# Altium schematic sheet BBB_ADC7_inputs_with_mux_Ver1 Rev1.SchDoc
size E
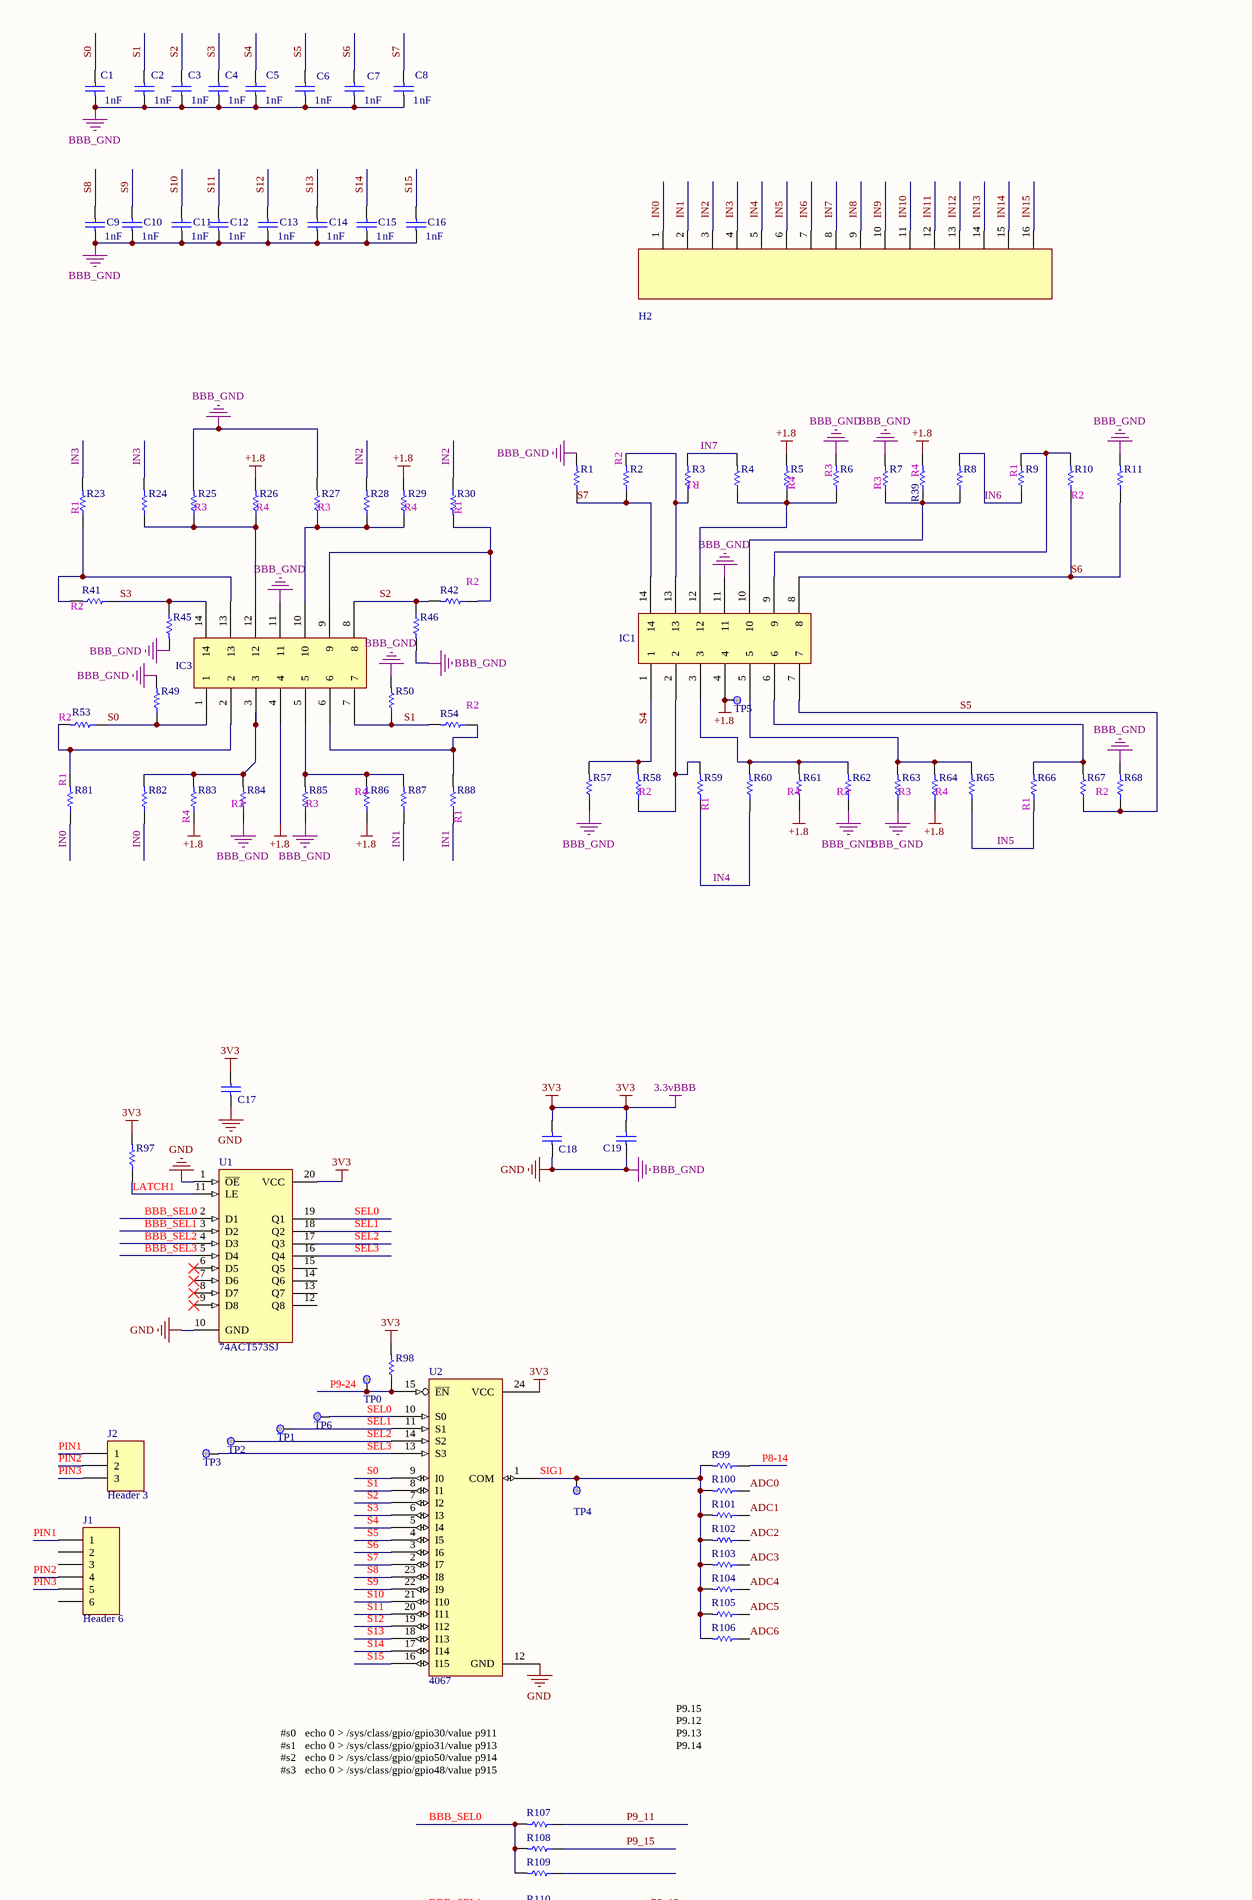
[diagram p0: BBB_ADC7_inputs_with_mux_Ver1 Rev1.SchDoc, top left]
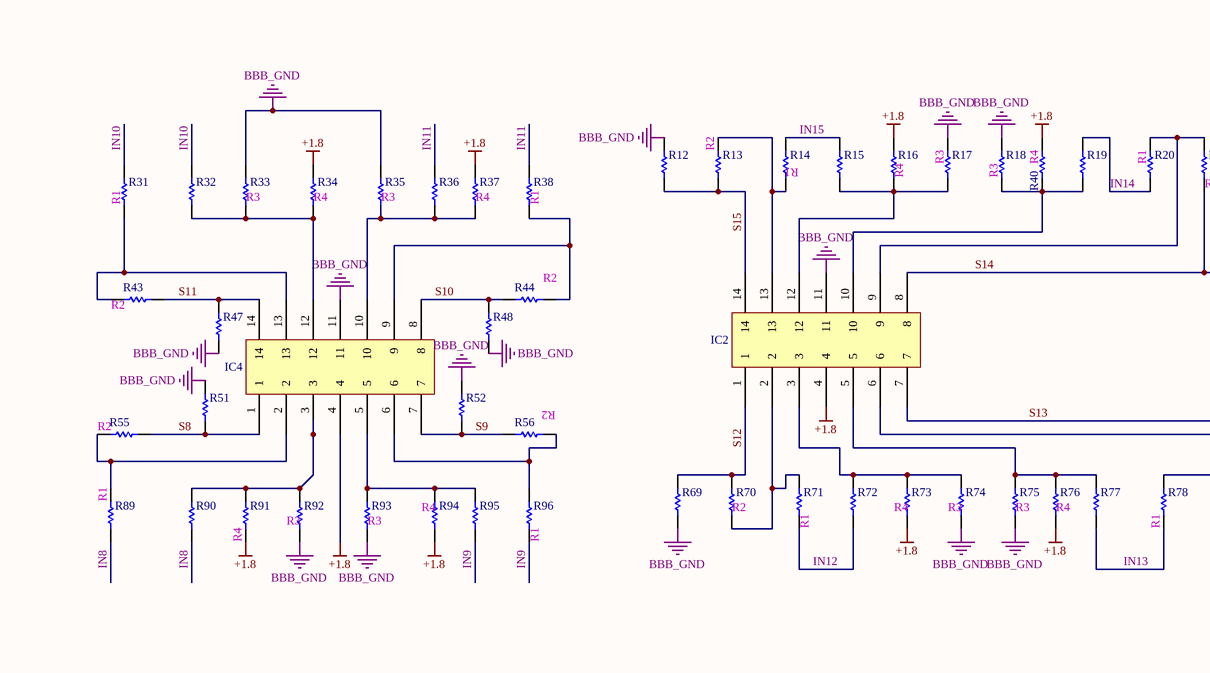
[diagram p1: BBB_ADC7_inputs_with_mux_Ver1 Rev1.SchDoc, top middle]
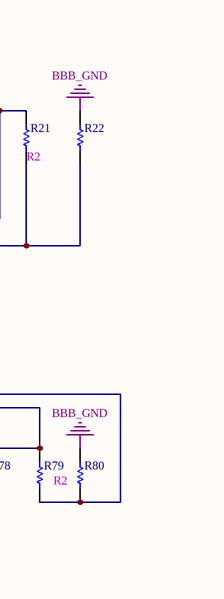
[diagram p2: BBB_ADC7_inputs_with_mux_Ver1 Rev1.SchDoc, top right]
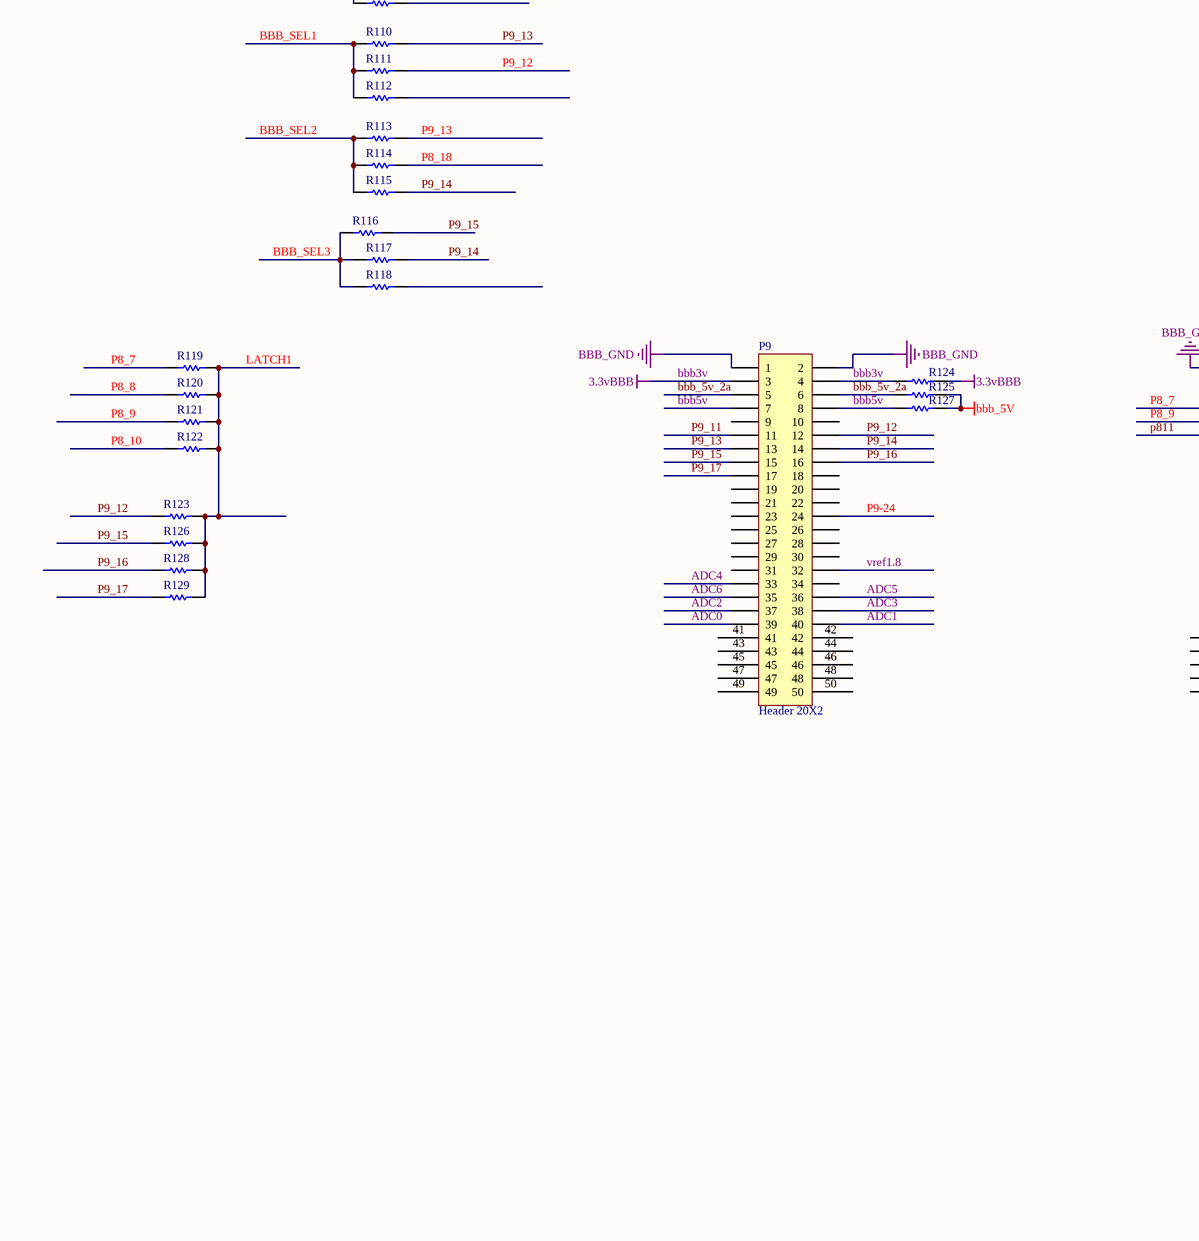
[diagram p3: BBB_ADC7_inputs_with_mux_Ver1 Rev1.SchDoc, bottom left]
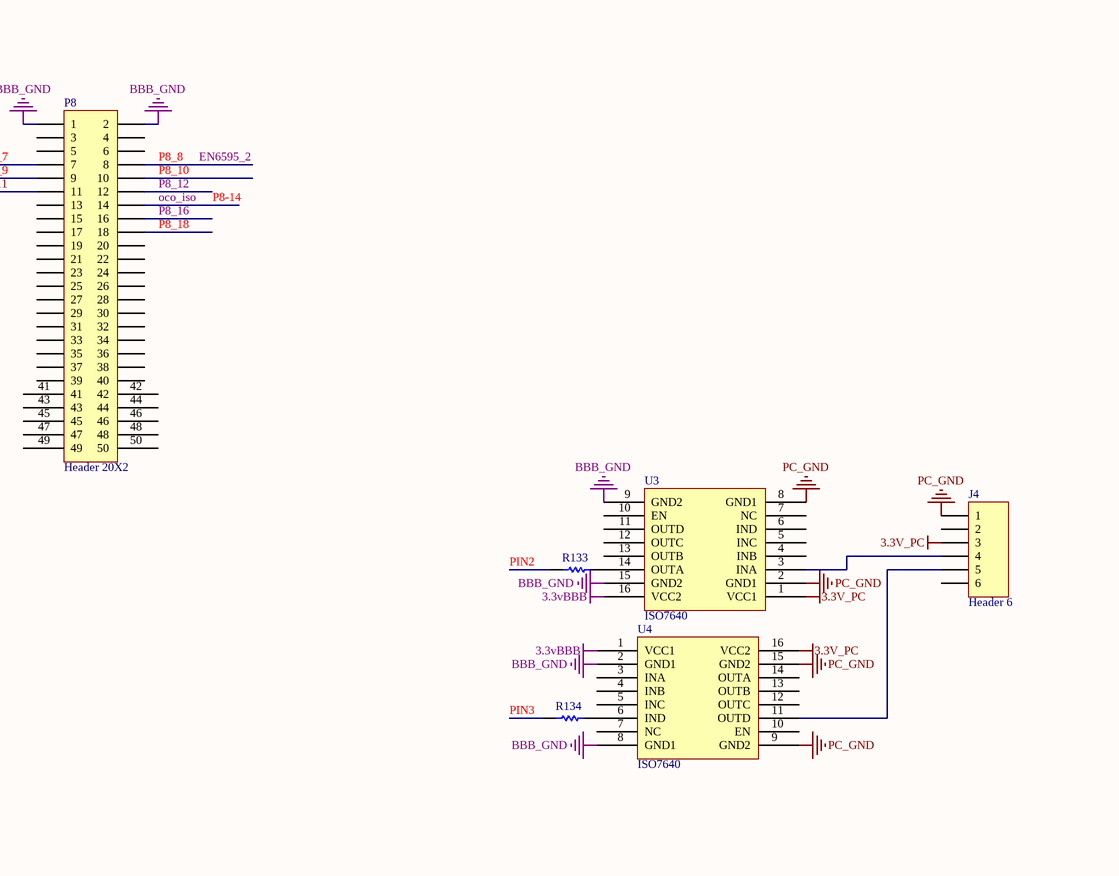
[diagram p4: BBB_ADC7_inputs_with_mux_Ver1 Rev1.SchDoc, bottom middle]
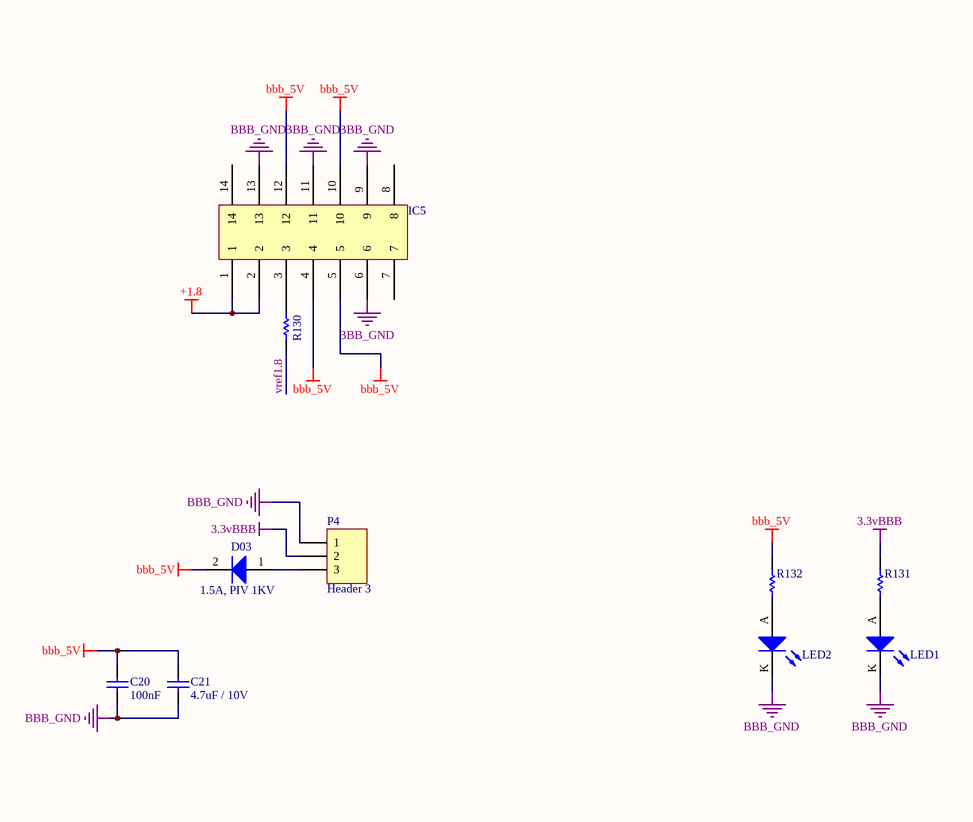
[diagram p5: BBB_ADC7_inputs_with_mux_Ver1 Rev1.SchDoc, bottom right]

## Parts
C1  Units of Capacitance: nF  Capacitance: 1  [C0402]  (hidden comment: CAPACITOR NONPOLAR SMT)
C2  Units of Capacitance: nF  Capacitance: 1  [C0402]  (hidden comment: CAPACITOR NONPOLAR SMT)
C3  Units of Capacitance: nF  Capacitance: 1  [C0402]  (hidden comment: CAPACITOR NONPOLAR SMT)
C4  Units of Capacitance: nF  Capacitance: 1  [C0402]  (hidden comment: CAPACITOR NONPOLAR SMT)
C5  Units of Capacitance: nF  Capacitance: 1  [C0402]  (hidden comment: CAPACITOR NONPOLAR SMT)
C6  Units of Capacitance: nF  Capacitance: 1  [C0402]  (hidden comment: CAPACITOR NONPOLAR SMT)
C7  Units of Capacitance: nF  Capacitance: 1  [C0402]  (hidden comment: CAPACITOR NONPOLAR SMT)
C8  Units of Capacitance: nF  Capacitance: 1  [C0402]  (hidden comment: CAPACITOR NONPOLAR SMT)
C9  Units of Capacitance: nF  Capacitance: 1  [C0402]  (hidden comment: CAPACITOR NONPOLAR SMT)
C10  Units of Capacitance: nF  Capacitance: 1  [C0402]  (hidden comment: CAPACITOR NONPOLAR SMT)
C11  Units of Capacitance: nF  Capacitance: 1  [C0402]  (hidden comment: CAPACITOR NONPOLAR SMT)
C12  Units of Capacitance: nF  Capacitance: 1  [C0402]  (hidden comment: CAPACITOR NONPOLAR SMT)
C13  Units of Capacitance: nF  Capacitance: 1  [C0402]  (hidden comment: CAPACITOR NONPOLAR SMT)
C14  Units of Capacitance: nF  Capacitance: 1  [C0402]  (hidden comment: CAPACITOR NONPOLAR SMT)
C15  Units of Capacitance: nF  Capacitance: 1  [C0402]  (hidden comment: CAPACITOR NONPOLAR SMT)
C16  Units of Capacitance: nF  Capacitance: 1  [C0402]  (hidden comment: CAPACITOR NONPOLAR SMT)
C17  4.7uF, 10V  [C0603]  (value not drawn)
C18  4.7uF, 10V  [C0603]  (value not drawn)
C19  4.7uF, 10V  [C0603]  (value not drawn)
C20  100nF  [C0603]
C21  4.7uF / 10V  [C0603]
D03  1.5A, PIV 1KV  [DIODE_DO-214AA(SMB)]
H2  connector 16 pin male_ stright  [16 pin male stright]  (value not drawn)
IC1  OPamp  [SOIC-14]  (value not drawn)
IC2  OPamp  [SOIC-14]  (value not drawn)
IC3  OPamp  [SOIC-14]  (value not drawn)
IC4  OPamp  [SOIC-14]  (value not drawn)
IC5  OPamp  [SOIC-14]  (value not drawn)
J1  Header 6  [HDR1X6]
J2  Header 3  [HDR1X3]
J4  Header 6  [HDR1X6]
LED1  LED  [0537, LED, 1206]  (value not drawn)
LED2  LED  [0537, LED, 1206]  (value not drawn)
P4  Header 3  [HDR1X3]
P8  Header 20X2  [BBBHEADERNOHOLE]
P9  Header 20X2  [BBBHEADERNOHOLE]
R1  Resistor SMD 0603, 100 k Ohm, +/-5%, 1/10W  [0603]  (value not drawn)
R2  Resistor SMD 0603, 1.5 k Ohm, +/-5%, 1/10W  [0603]  (value not drawn)
R3  Resistor SMD 0603, 9.1 k Ohm, +/-5%, 1/10W  [0603]  (value not drawn)
R4  open  [0603]  (value not drawn)
R5  Resistor SMD 0603, 6.8 k Ohm, +/-1%, 1/10W  [0603]  (value not drawn)
R6  Resistor SMD 0603, 4.7 k Ohm, +/-5%, 1/10W  [0603]  (value not drawn)
R7  Resistor SMD 0603, 4.7 k Ohm, +/-5%, 1/10W  [0603]  (value not drawn)
R8  open  [0603]  (value not drawn)
R9  Resistor SMD 0603, 9.1 k Ohm, +/-5%, 1/10W  [0603]  (value not drawn)
R10  Resistor SMD 0603, 1.5 k Ohm, +/-5%, 1/10W  [0603]  (value not drawn)
R11  Resistor SMD 0603, 100 k Ohm, +/-5%, 1/10W  [0603]  (value not drawn)
R12  Resistor SMD 0603, 100 k Ohm, +/-5%, 1/10W  [0603]  (value not drawn)
R13  Resistor SMD 0603, 1.5 k Ohm, +/-5%, 1/10W  [0603]  (value not drawn)
R14  Resistor SMD 0603, 9.1 k Ohm, +/-5%, 1/10W  [0603]  (value not drawn)
R15  open  [0603]  (value not drawn)
R16  Resistor SMD 0603, 6.8 k Ohm, +/-1%, 1/10W  [0603]  (value not drawn)
R17  Resistor SMD 0603, 4.7 k Ohm, +/-5%, 1/10W  [0603]  (value not drawn)
R18  Resistor SMD 0603, 4.7 k Ohm, +/-5%, 1/10W  [0603]  (value not drawn)
R19  open  [0603]  (value not drawn)
R20  Resistor SMD 0603, 9.1 k Ohm, +/-5%, 1/10W  [0603]  (value not drawn)
R21  Resistor SMD 0603, 1.5 k Ohm, +/-5%, 1/10W  [0603]  (value not drawn)
R22  Resistor SMD 0603, 100 k Ohm, +/-5%, 1/10W  [0603]  (value not drawn)
R23  Resistor SMD 0603, 9.1 k Ohm, +/-5%, 1/10W  [0603]  (value not drawn)
R24  OPEN  [0603]  (value not drawn)
R25  Resistor SMD 0603, 4.7 k Ohm, +/-5%, 1/10W  [0603]  (value not drawn)
R26  Resistor SMD 0603, 6.8 k Ohm, +/-1%, 1/10W  [0603]  (value not drawn)
R27  Resistor SMD 0603, 4.7 k Ohm, +/-5%, 1/10W  [0603]  (value not drawn)
R28  OPEN  [0603]  (value not drawn)
R29  Resistor SMD 0603, 6.8 k Ohm, +/-1%, 1/10W  [0603]  (value not drawn)
R30  Resistor SMD 0603, 9.1 k Ohm, +/-5%, 1/10W  [0603]  (value not drawn)
R31  Resistor SMD 0603, 9.1 k Ohm, +/-5%, 1/10W  [0603]  (value not drawn)
R32  OPEN  [0603]  (value not drawn)
R33  Resistor SMD 0603, 4.7 k Ohm, +/-5%, 1/10W  [0603]  (value not drawn)
R34  Resistor SMD 0603, 6.8 k Ohm, +/-1%, 1/10W  [0603]  (value not drawn)
R35  Resistor SMD 0603, 4.7 k Ohm, +/-5%, 1/10W  [0603]  (value not drawn)
R36  OPEN  [0603]  (value not drawn)
R37  Resistor SMD 0603, 6.8 k Ohm, +/-1%, 1/10W  [0603]  (value not drawn)
R38  Resistor SMD 0603, 9.1 k Ohm, +/-5%, 1/10W  [0603]  (value not drawn)
R39  Resistor SMD 0603, 6.8 k Ohm, +/-1%, 1/10W  [0603]  (value not drawn)
R40  Resistor SMD 0603, 6.8 k Ohm, +/-1%, 1/10W  [0603]  (value not drawn)
R41  Resistor SMD 0603, 1.5 k Ohm, +/-5%, 1/10W  [0603]  (value not drawn)
R42  Resistor SMD 0603, 1.5 k Ohm, +/-5%, 1/10W  [0603]  (value not drawn)
R43  Resistor SMD 0603, 1.5 k Ohm, +/-5%, 1/10W  [0603]  (value not drawn)
R44  Resistor SMD 0603, 1.5 k Ohm, +/-5%, 1/10W  [0603]  (value not drawn)
R45  Resistor SMD 0603, 100 k Ohm, +/-5%, 1/10W  [0603]  (value not drawn)
R46  Resistor SMD 0603, 100 k Ohm, +/-5%, 1/10W  [0603]  (value not drawn)
R47  Resistor SMD 0603, 100 k Ohm, +/-5%, 1/10W  [0603]  (value not drawn)
R48  Resistor SMD 0603, 100 k Ohm, +/-5%, 1/10W  [0603]  (value not drawn)
R49  Resistor SMD 0603, 100 k Ohm, +/-5%, 1/10W  [0603]  (value not drawn)
R50  Resistor SMD 0603, 100 k Ohm, +/-5%, 1/10W  [0603]  (value not drawn)
R51  Resistor SMD 0603, 100 k Ohm, +/-5%, 1/10W  [0603]  (value not drawn)
R52  Resistor SMD 0603, 100 k Ohm, +/-5%, 1/10W  [0603]  (value not drawn)
R53  Resistor SMD 0603, 1.5 k Ohm, +/-5%, 1/10W  [0603]  (value not drawn)
R54  Resistor SMD 0603, 1.5 k Ohm, +/-5%, 1/10W  [0603]  (value not drawn)
R55  Resistor SMD 0603, 1.5 k Ohm, +/-5%, 1/10W  [0603]  (value not drawn)
R56  Resistor SMD 0603, 1.5 k Ohm, +/-5%, 1/10W  [0603]  (value not drawn)
R57  Resistor SMD 0603, 100 k Ohm, +/-5%, 1/10W  [0603]  (value not drawn)
R58  Resistor SMD 0603, 1.5 k Ohm, +/-5%, 1/10W  [0603]  (value not drawn)
R59  Resistor SMD 0603, 9.1 k Ohm, +/-5%, 1/10W  [0603]  (value not drawn)
R60  open  [0603]  (value not drawn)
R61  Resistor SMD 0603, 6.8 k Ohm, +/-1%, 1/10W  [0603]  (value not drawn)
R62  Resistor SMD 0603, 4.7 k Ohm, +/-5%, 1/10W  [0603]  (value not drawn)
R63  Resistor SMD 0603, 4.7 k Ohm, +/-5%, 1/10W  [0603]  (value not drawn)
R64  Resistor SMD 0603, 6.8 k Ohm, +/-1%, 1/10W  [0603]  (value not drawn)
R65  open  [0603]  (value not drawn)
R66  Resistor SMD 0603, 9.1 k Ohm, +/-5%, 1/10W  [0603]  (value not drawn)
R67  Resistor SMD 0603, 1.5 k Ohm, +/-5%, 1/10W  [0603]  (value not drawn)
R68  Resistor SMD 0603, 100 k Ohm, +/-5%, 1/10W  [0603]  (value not drawn)
R69  Resistor SMD 0603, 100 k Ohm, +/-5%, 1/10W  [0603]  (value not drawn)
R70  Resistor SMD 0603, 1.5 k Ohm, +/-5%, 1/10W  [0603]  (value not drawn)
R71  Resistor SMD 0603, 9.1 k Ohm, +/-5%, 1/10W  [0603]  (value not drawn)
R72  open  [0603]  (value not drawn)
R73  Resistor SMD 0603, 6.8 k Ohm, +/-1%, 1/10W  [0603]  (value not drawn)
R74  Resistor SMD 0603, 4.7 k Ohm, +/-5%, 1/10W  [0603]  (value not drawn)
R75  Resistor SMD 0603, 4.7 k Ohm, +/-5%, 1/10W  [0603]  (value not drawn)
R76  Resistor SMD 0603, 6.8 k Ohm, +/-1%, 1/10W  [0603]  (value not drawn)
R77  open  [0603]  (value not drawn)
R78  Resistor SMD 0603, 9.1 k Ohm, +/-5%, 1/10W  [0603]  (value not drawn)
R79  Resistor SMD 0603, 1.5 k Ohm, +/-5%, 1/10W  [0603]  (value not drawn)
R80  Resistor SMD 0603, 100 k Ohm, +/-5%, 1/10W  [0603]  (value not drawn)
R81  Resistor SMD 0603, 9.1 k Ohm, +/-5%, 1/10W  [0603]  (value not drawn)
R82  OPEN  [0603]  (value not drawn)
R83  Resistor SMD 0603, 6.8 k Ohm, +/-1%, 1/10W  [0603]  (value not drawn)
R84  Resistor SMD 0603, 4.7 k Ohm, +/-5%, 1/10W  [0603]  (value not drawn)
R85  Resistor SMD 0603, 4.7 k Ohm, +/-5%, 1/10W  [0603]  (value not drawn)
R86  Resistor SMD 0603, 6.8 k Ohm, +/-1%, 1/10W  [0603]  (value not drawn)
R87  OPEN  [0603]  (value not drawn)
R88  Resistor SMD 0603, 9.1 k Ohm, +/-5%, 1/10W  [0603]  (value not drawn)
R89  Resistor SMD 0603, 9.1 k Ohm, +/-5%, 1/10W  [0603]  (value not drawn)
R90  OPEN  [0603]  (value not drawn)
R91  Resistor SMD 0603, 6.8 k Ohm, +/-1%, 1/10W  [0603]  (value not drawn)
R92  Resistor SMD 0603, 4.7 k Ohm, +/-5%, 1/10W  [0603]  (value not drawn)
R93  Resistor SMD 0603, 4.7 k Ohm, +/-5%, 1/10W  [0603]  (value not drawn)
R94  Resistor SMD 0603, 6.8 k Ohm, +/-1%, 1/10W  [0603]  (value not drawn)
R95  OPEN  [0603]  (value not drawn)
R96  Resistor SMD 0603, 9.1 k Ohm, +/-5%, 1/10W  [0603]  (value not drawn)
R97  (no value)  [0603]
R98  1Kohm  [0603]  (value not drawn)
R99  1Kohm  [0603]  (value not drawn)
R100  1Kohm  [0603]  (value not drawn)
R101  1Kohm  [0603]  (value not drawn)
R102  1Kohm  [0603]  (value not drawn)
R103  1Kohm  [0603]  (value not drawn)
R104  1Kohm  [0603]  (value not drawn)
R105  1Kohm  [0603]  (value not drawn)
R106  1Kohm  [0603]  (value not drawn)
R107  (no value)  [0603]
R108  (no value)  [0603]
R109  (no value)  [0603]
R110  (no value)  [0603]
R111  (no value)  [0603]
R112  (no value)  [0603]
R113  (no value)  [0603]
R114  (no value)  [0603]
R115  (no value)  [0603]
R116  (no value)  [0603]
R117  (no value)  [0603]
R118  (no value)  [0603]
R119  1Kohm  [0603]  (value not drawn)
R120  1Kohm  [0603]  (value not drawn)
R121  1Kohm  [0603]  (value not drawn)
R122  1Kohm  [0603]  (value not drawn)
R123  1Kohm  [0603]  (value not drawn)
R124  Resistor SMD 0603, 0 Ohm, +/-5%, 1/10W  [0603]  (value not drawn)
R125  Resistor SMD 0603, 0 Ohm, +/-5%, 1/10W  [0603]  (value not drawn)
R126  1Kohm  [0603]  (value not drawn)
R127  Resistor SMD 0603, 0 Ohm, +/-5%, 1/10W  [0603]  (value not drawn)
R128  1Kohm  [0603]  (value not drawn)
R129  1Kohm  [0603]  (value not drawn)
R130  Resistor SMD 0603, 0 Ohm, +/-5%, 1/10W  [0603]  (value not drawn)
R131  Resistor SMD 0603, 4.7 k Ohm, +/-5%, 1/10W  [0603]  (value not drawn)
R132  Resistor SMD 0603, 4.7 k Ohm, +/-5%, 1/10W  [0603]  (value not drawn)
R133  Resistor SMD 0603, 0 Ohm, +/-5%, 1/10W  [0603]  (value not drawn)
R134  Resistor SMD 0603, 0 Ohm, +/-5%, 1/10W  [0603]  (value not drawn)
TP0  TEST PAD  [TP]  (value not drawn)
TP1  TEST PAD  [TP]  (value not drawn)
TP2  TEST PAD  [TP]  (value not drawn)
TP3  TEST PAD  [TP]  (value not drawn)
TP4  TEST PAD  [TP]  (value not drawn)
TP5  TEST PAD  [TP]  (value not drawn)
TP6  TEST PAD  [TP]  (value not drawn)
U1  74ACT573SJ  [sol-20]
U2  4067  [SSOP-24]
U3  ISO7640  [SOIC-16]
U4  ISO7640  [SOIC-16]

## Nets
3.3V_PC: J4.3 U3.1(VCC1) U4.16(VCC2)
+1.8: IC1.4 IC2.4 IC3.4 IC4.4 IC5.1 IC5.2 R5.2 R16.2 R26.2 R29.2 R34.2 R37.2 R39.2 R40.2 R61.1 R64.1 R73.1 R76.1 R83.1 R86.1 R91.1 R94.1 TP5.1
bbb3v: C17.1 C18.1 C19.1 P4.2 P9.3 P9.4 R97.2 R98.2 R124.1 R124.2 R131.2 U1.20(VCC) U2.24(VCC) U3.16(VCC2) U4.1(VCC1)  [also labelled 3.3vBBB, 3V3]
bbb_5V: C20.1 C21.1 D03.2 IC5.4 IC5.5 IC5.10 IC5.12 R125.1 R127.1 R132.2
BBB_GND: C1.2 C2.2 C3.2 C4.2 C5.2 C6.2 C7.2 C8.2 C9.2 C10.2 C11.2 C12.2 C13.2 C14.2 C15.2 C16.2 C17.2 C18.2 C19.2 C20.2 C21.2 IC1.11 IC2.11 IC3.11 IC4.11 IC5.6 IC5.9 IC5.11 IC5.13 LED1.K LED2.K P4.1 P8.1 P8.2 P9.1 P9.2 R1.2 R6.2 R7.2 R11.2 R12.2 R17.2 R18.2 R22.2 R25.2 R27.2 R33.2 R35.2 R45.2 R46.2 R47.2 R48.2 R49.2 R50.2 R51.2 R52.2 R57.1 R62.1 R63.1 R68.2 R69.1 R74.1 R75.1 R80.2 R84.1 R85.1 R92.1 R93.1 U1.1(~{OE}) U1.10(GND) U2.12(GND) U3.9(GND2) U3.15(GND2) U4.2(GND1) U4.8(GND1)  [also labelled GND]
PC_GND: J4.1 U3.2(GND1) U3.8(GND1) U4.9(GND2) U4.15(GND2)
ADC0: P9.39 R100.1
ADC1: P9.40 R101.1
ADC2: P9.37 R102.1
ADC3: P9.38 R103.1
ADC4: P9.33 R104.1
ADC5: P9.36 R105.1
ADC6: P9.35 R106.1
bbb5v: P9.7 P9.8 R127.2
bbb_5v_2a: P9.5 P9.6 R125.2
BBB_SEL0: R107.2 R108.2 R109.2 U1.2(D1)
BBB_SEL1: R110.2 R111.2 R112.2 U1.3(D2)
BBB_SEL2: R113.2 R114.2 R115.2 U1.4(D3)
BBB_SEL3: R116.2 R117.2 R118.2 U1.5(D4)
EN6595_2: P8.8 R120.2  [also labelled P8_8]
IN0: H2.1 R81.1 R82.1
IN1: H2.2 R87.1 R88.1
IN2: H2.3 R28.2 R30.1
IN3: H2.4 R23.2 R24.2
IN4: H2.5 R59.1 R60.1
IN5: H2.6 R65.1 R66.1
IN6: H2.7 R8.2 R9.1
IN7: H2.8 R3.2 R4.2
IN8: H2.9 R89.1 R90.1
IN9: H2.10 R95.1 R96.1
IN10: H2.11 R31.2 R32.2
IN11: H2.12 R36.2 R38.1
IN12: H2.13 R71.1 R72.1
IN13: H2.14 R77.1 R78.1
IN14: H2.15 R19.2 R20.1
IN15: H2.16 R14.2 R15.2
LATCH1: R97.1 R119.1 R120.1 R121.1 R122.1 R123.1 R126.1 R128.1 R129.1 U1.11(LE)
oco_iso: P8.14 R99.1  [also labelled P8-14]
P8_7: P8.7 R119.2
P8_9: P8.9 R121.2
P8_10: P8.10 R122.2
P8_12: P8.12
P8_16: P8.16
P8_18: P8.18 R114.1
P9-24: P9.24 R98.1 TP0.1 U2.15(~{EN})
P9_11: P9.11 R107.1
P9_12: P9.12 R111.1 R123.2
P9_13: P9.13 R110.1 R113.1
P9_14: P9.14 R115.1 R117.1
P9_15: P9.15 R108.1 R116.1 R126.2
P9_16: P9.16 R128.2
P9_17: P9.17 R129.2
p811: P8.11
PIN1: J1.1 J2.1
PIN2: J1.4 J2.2 R133.2
PIN3: J1.5 J2.3 R134.2
S0: C1.1 IC3.1 R49.1 R53.1 U2.9(I0)
S1: C2.1 IC3.7 R50.1 R54.2 U2.8(I1)
S2: C3.1 IC3.8 R42.2 R46.1 U2.7(I2)
S3: C4.1 IC3.14 R41.1 R45.1 U2.6(I3)
S4: C5.1 IC1.1 R57.2 R58.2 U2.5(I4)
S5: C6.1 IC1.7 R67.1 R68.1 U2.4(I5)
S6: C7.1 IC1.8 R10.1 R11.1 U2.3(I6)
S7: C8.1 IC1.14 R1.1 R2.1 U2.2(I7)
S8: C9.1 IC4.1 R51.1 R55.1 U2.23(I8)
S9: C10.1 IC4.7 R52.1 R56.2 U2.22(I9)
S10: C11.1 IC4.8 R44.2 R48.1 U2.21(I10)
S11: C12.1 IC4.14 R43.1 R47.1 U2.20(I11)
S12: C13.1 IC2.1 R69.2 R70.2 U2.19(I12)
S13: C14.1 IC2.7 R79.1 R80.1 U2.18(I13)
S14: C15.1 IC2.8 R21.1 R22.1 U2.17(I14)
S15: C16.1 IC2.14 R12.1 R13.1 U2.16(I15)
SEL0: TP6.1 U1.19(Q1) U2.10(S0)
SEL1: TP1.1 U1.18(Q2) U2.11(S1)
SEL2: TP2.1 U1.17(Q3) U2.14(S2)
SEL3: TP3.1 U1.16(Q4) U2.13(S3)
SIG1: R99.2 R100.2 R101.2 R102.2 R103.2 R104.2 R105.2 R106.2 TP4.1 U2.1(COM)
vref1.8: P9.32 R130.1
NetD03_1: D03.1 P4.3
NetIC1_2: IC1.2 R58.1 R59.2
NetIC1_3: IC1.3 R60.2 R61.2 R62.2
NetIC1_5: IC1.5 R63.2 R64.2 R65.2
NetIC1_6: IC1.6 R66.2 R67.2
NetIC1_9: IC1.9 R9.2 R10.2
NetIC1_10: IC1.10 R7.1 R8.1 R39.1
NetIC1_12: IC1.12 R4.1 R5.1 R6.1
NetIC1_13: IC1.13 R2.2 R3.1
NetIC2_2: IC2.2 R70.1 R71.2
NetIC2_3: IC2.3 R72.2 R73.2 R74.2
NetIC2_5: IC2.5 R75.2 R76.2 R77.2
NetIC2_6: IC2.6 R78.2 R79.2
NetIC2_9: IC2.9 R20.2 R21.2
NetIC2_10: IC2.10 R18.1 R19.1 R40.1
NetIC2_12: IC2.12 R15.1 R16.1 R17.1
NetIC2_13: IC2.13 R13.2 R14.1
NetIC3_2: IC3.2 R53.2 R81.2
NetIC3_3: IC3.3 R82.2 R83.2 R84.2
NetIC3_5: IC3.5 R85.2 R86.2 R87.2
NetIC3_6: IC3.6 R54.1 R88.2
NetIC3_9: IC3.9 R30.2 R42.1
NetIC3_10: IC3.10 R27.1 R28.1 R29.1
NetIC3_12: IC3.12 R24.1 R25.1 R26.1
NetIC3_13: IC3.13 R23.1 R41.2
NetIC4_2: IC4.2 R55.2 R89.2
NetIC4_3: IC4.3 R90.2 R91.2 R92.2
NetIC4_5: IC4.5 R93.2 R94.2 R95.2
NetIC4_6: IC4.6 R56.1 R96.2
NetIC4_9: IC4.9 R38.2 R44.1
NetIC4_10: IC4.10 R35.1 R36.1 R37.1
NetIC4_12: IC4.12 R32.1 R33.1 R34.1
NetIC4_13: IC4.13 R31.1 R43.2
NetIC5_3: IC5.3 R130.2
NetJ4_4: J4.4 U3.3(INA)
NetJ4_5: J4.5 U4.11(OUTD)
NetLED1_A: LED1.A R131.1
NetLED2_A: LED2.A R132.1
NetR133_1: R133.1 U3.14(OUTA)
NetR134_1: R134.1 U4.6(IND)

Not connected (* = marked no-connect by the designer): IC5 7 8 14; J1 2 3 6; J4 2 6; P8 3 4 5 6 13 15 17 19 20 21 22 23 24 25 26 27 28 29 30 31 32 33 34 35 36 37 38 39 40 41 42 43 44 45 46 47 48 49 50; P9 9 10 18 19 20 21 22 23 25 26 27 28 29 30 31 34 41 42 43 44 45 46 47 48 49 50; R109 1; R112 1; R118 1; U1 6(D5)* 7(D6)* 8(D7)* 9(D8)* 12(Q8) 13(Q7) 14(Q6) 15(Q5); U3 4(INB) 5(INC) 6(IND) 7(NC) 10(EN) 11(OUTD) 12(OUTC) 13(OUTB); U4 3(INA) 4(INB) 5(INC) 7(NC) 10(EN) 12(OUTC) 13(OUTB) 14(OUTA)

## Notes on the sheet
- (near R2) R2
- (near R3) R1
- (near R5) R4
- (near R6) R3
- (near R7) R3
- (near R39) R4
- (near R9) R1
- (near R10) R2
- (near R13) R2
- (near R14) R1
- (near R16) R4
- (near R17) R3
- (near R18) R3
- (near R40) R4
- (near R20) R1
- (near R21) R2
- (near R23) R1
- (near R25) R3
- (near R26) R4
- (near R27) R3
- (near R29) R4
- (near R30) R1
- (near R31) R1
- (near R33) R3
- (near R34) R4
- (near R35) R3
- (near R37) R4
- (near R38) R1
- (near R41) R2
- (near R42) R2
- (near R43) R2
- (near R44) R2
- (near R53) R2
- (near R54) R2
- (near R55) R2
- (near R56) R2
- (near R81) R1
- (near R84) R3
- (near R85) R3
- (near R86) R4
- (near R58) R2
- (near R59) R1
- (near R61) R4
- (near R62) R3
- (near R63) R3
- (near R64) R4
- (near R66) R1
- R2
- (near R89) R1
- (near R92) R3
- (near R93) R3
- (near R94) R4
- (near R70) R2
- (near R71) R1
- (near R73) R4
- (near R74) R3
- (near R75) R3
- (near R76) R4
- (near R78) R1
- (near R83) R4
- (near R88) R1
- (near R91) R4
- (near R96) R1
- (near R107) #s0   echo 0 > /sys/class/gpio/gpio30/value p911
  #s1   echo 0 > /sys/class/gpio/gpio31/value p913
  #s2   echo 0 > /sys/class/gpio/gpio50/value p914
  #s3   echo 0 > /sys/class/gpio/gpio48/value p915
- P9.15
  P9.12
  P9.13
  P9.14

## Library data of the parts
C1-C16 = BCS22A-102: Capacitor ceramic, SMD 0402, 1 nF, +/-10%, 50 V dc; Mfr Name: YAGEO; Secure Use Status: Preferred; Voltage Rating: 50; Units of Voltage: V dc; Dielectric: X7R; Value(Farad): 1n
C17-C19 C21 = BCS129-475: Capacitor ceramic, SMD 0603, 4.7 uF, +/-10%, 10 V dc; Mfr Name: KEMET; Secure Use Status: Authorization Required; Voltage Rating: 10; Units of Voltage: V dc; Capacitance: 4.7; Dielectric: X5R; 3D Model: Not Required
C20 = BCS129-104: Capacitor ceramic, SMD 0603, 100 nF, +/-10%, 16 V dc; Mfr Name: KEMET; Units of Voltage: V dc; Value(Farad): 100n; Voltage Rating: 16; Dielectric: X7R; Capacitance: 100
D03 = BDS334-001: Diode high voltage, SMD DO-214AA, If 1.5 A, PIV 1 kV; Mfr Name: VISHAY; Secure Use Status: Authorization Required; Peak Inverse Voltage: 1; Average Forward Current: 1.5
IC1-IC4 = OPamp: SMLPARTNO: BIS114-020
IC5 = OPamp: SMLPPARTNO: BIS114-020
J1 J4 = Header 6: Header, 6-Pin
J2 P4 = Header 3: Header, 3-Pin
LED1 LED2 = BDS461-001: Optoelectronic LED, SMD 1206, red colour; Mfr Name: AVAGO TECHNOLOGIES
P8 P9 = Header 20X2: Header, 20-Pin, Dual row
R1 R11 R12 R22 R45-R52 R57 R68 R69 R80 = BRS133-473: SMLPARTNO: BRS131-104; Mfr Name: VISHAY; Sub Category: Thick Film; Tempco1: 0.0002; Unit Of Resistance: k Ohm; Value(ohm): 100
R2 R13 R41-R44 R53-R56 R58 R67 R70 R79 = BRS133-473: SMLPARTNO: BRS131-152; Mfr Name: VISHAY; Sub Category: Thick Film; Tempco1: 0.0002; Unit Of Resistance: k Ohm; Value(ohm): 1.5
R3 R9 R14 R20 R30 R38 R66 R78 R81 R88 R89 R96 = BRS133-473: SMLPARTNO: BRS131-912; Mfr Name: VISHAY; Sub Category: Thick Film; Tempco1: 0.0002; Unit Of Resistance: k Ohm; Value(ohm): 9.1
R4 R8 R15 R19 R24 R28 R32 R36 R60 R72 R82 R87 R90 R95 = BRS133-473: Mfr Name: VISHAY; Sub Category: Thick Film; Tempco1: 0.0002; Tolerance: +/-5%; Power Rating: 1/10W
R5 R16 R26 R34 R39 R40 R61 R64 R73 R76 R86 R94 = BRS133-473: SMLPARTNO: BRS131-682; Mfr Name: VISHAY; Sub Category: Thick Film; Tempco1: 0.0002; Unit Of Resistance: k Ohm; Value(ohm): 6.5; Tolerance: +/-5%
R6 R7 R17 R18 R25 R27 R33 R35 R62 R63 R74 R75 R84 R85 R92 R93 = BRS133-473: SMLPARTNO: BRS133-472; Mfr Name: VISHAY; Sub Category: Thick Film; Tempco1: 0.0002; Unit Of Resistance: k Ohm; Value(ohm): 4.7
R10 R21 = BRS133-473: SMLPARTNO: BRS131-152; Mfr Name: VISHAY; Sub Category: Thick Film; Resistance: 47; Tempco1: 0.0002; Unit Of Resistance: k Ohm; Value(ohm): 1.5
R23 R31 = BRS133-473: SMLPARTNO: BRS131-912; Mfr Name: VISHAY; Sub Category: Thick Film; Resistance: 47; Tempco1: 0.0002; Unit Of Resistance: k Ohm; Value(ohm): 9.1
R29 R37 R83 R91 = BRS133-473: SMLPARTNO: BRS131-682; Mfr Name: VISHAY; Sub Category: Thick Film; Resistance: 47; Tempco1: 0.0002; Unit Of Resistance: k Ohm; Value(ohm): 6.5; Tolerance: +/-5%
R59 R71 = BRS133-473: SMLPARTNO: BRS133-902; Mfr Name: VISHAY; Sub Category: Thick Film; Tempco1: 0.0002; Unit Of Resistance: k Ohm; Value(ohm): 9.2
R65 R77 = BRS133-473: Mfr Name: VISHAY; Sub Category: Thick Film; Tempco1: 0.0002; Unit Of Resistance: k Ohm; Tolerance: +/-5%; Power Rating: 1/10W
R97 R107-R118 = BRS132-472: Resistor SMD 0603, 0 Ohm, +/-5%, 1/10W; SMLPARTNO: BRS132-000; Mfr Name: YAGEO; Sub Category: Thick Film; Resistance: 0; Tempco1: 0.0001; Unit Of Resistance: k Ohm; Value(ohm): 4.7k
R98-R106 R119-R123 R126 R128 R129 = BRS831-102: Resistor SMD 0603, 1 k Ohm, +/-1%, 1/10W; Mfr Name: YAGEO; Sub Category: Thin Film; Resistance: 1; Tempco1: 0.00005; Unit Of Resistance: k Ohm; Value(ohm): 1k
R124 R125 R127 R133 R134 = BRS133-473: SMLPARTNO: BRS133-000; Mfr Name: VISHAY; Sub Category: Thick Film; Tempco1: 0.0002; Value(ohm): 0
R130 = BRS133-473: SMLPARTNO: BRS133-000; Mfr Name: VISHAY; Sub Category: Thick Film; Resistance: 47; Tempco1: 0.0002; Value(ohm): 0
R131 R132 = BRS831-102: SMLPARTNO: BRS133-472; Mfr Name: YAGEO; Sub Category: Thin Film; Tempco1: 0.00005; Unit Of Resistance: k Ohm; Value(ohm): 4.7; Tolerance: +/-1%
U1 = 74ACT573SJ: Octal Latch with 3-State Output
U2 = MUX-74HC4067
U3 U4 = BIS116-038: IC digital isolator SMD SOIC-16, ISO7640; Mfr Name: TEXAS INSTRUMENTS; LED Colour: Not Applicable; 3D Model: Required; Sub Category: Opto Coupler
